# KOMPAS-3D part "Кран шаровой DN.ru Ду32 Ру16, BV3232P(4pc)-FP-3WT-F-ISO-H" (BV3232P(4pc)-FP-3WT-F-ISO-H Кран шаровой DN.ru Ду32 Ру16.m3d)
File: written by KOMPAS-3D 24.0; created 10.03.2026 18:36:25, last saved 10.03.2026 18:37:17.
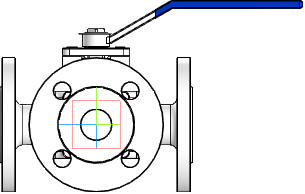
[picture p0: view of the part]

Document properties: Автор: R2D2; Полное имя файла: E:\Работа\Зайцев\BV3232P(4pc)-FP-3WT-F-ISO-H Кран шаровой DN.ru Ду15-100 Ру16\DN32\BV3232P(4pc)-FP-3WT-F-ISO-H Кран шаровой DN.ru Ду32 Ру16.m3d

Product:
- Part/product: Кран шаровой DN.ru Ду32 Ру16  | designation BV3232P(4pc)-FP-3WT-F-ISO-H
    Масса: 9.3
    Раздел спецификации: Прочие изделия
    Примечание: D160-36349

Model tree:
1. Операция без истории:1

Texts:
  BV3232P(4pc)-FP-3WT-F-ISO-H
